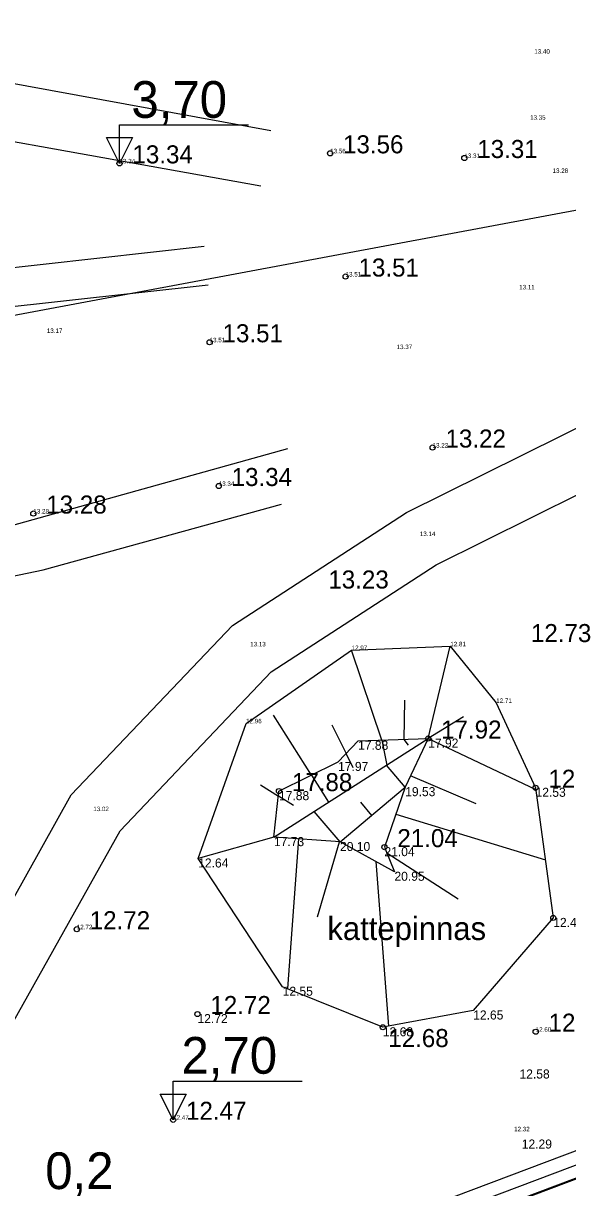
# Model space of a CAD drawing. Extents: x 433497 to 434382, y 6534486 to 6534993.
# Drawn here: x 433653.5 to 433695.8, y 6534629.3 to 6534719.6 of the extents above; entities that cross this region are included whole.
import ezdxf

# ---------------------------------------------------------------- set-up
doc = ezdxf.new("R2010")
doc.units = 0
for name, color, linetype in [('Default', 7, 'Continuous'), ('GEOLPUNKT', 7, 'Continuous'), ('jääkpaksus', 7, 'Continuous'), ('kataster', 7, 'Continuous'), ('KORGUS-EH2000', 7, 'Continuous'), ('l__x00e4__bil__x00f5__iked', 7, 'Continuous'), ('MOOTKORG-EH2000', 7, 'Continuous'), ('PIIR', 7, 'Continuous'), ('RELJEEF', 7, 'Continuous'), ('TEE', 7, 'Continuous')]:
    doc.layers.add(name, color=color, linetype=linetype)

msp = doc.modelspace()

# ---------------------------------------------------------------- linework, layer by layer
at = {"layer": 'Default'}
msp.add_lwpolyline([(433617.12, 6534791.025), (433632.75, 6534606.045), (434137.38, 6534796.515), (434127.69, 6534855.6), (433968.21, 6534911.925), (433942.38, 6534904.035), (433920.99, 6534907.275)], close=True, dxfattribs=at)
msp.add_lwpolyline([(433617.12, 6534791.025), (433632.75, 6534606.045), (434137.38, 6534796.515), (434127.69, 6534855.6), (433968.21, 6534911.925), (433942.38, 6534904.035), (433920.99, 6534907.275)], close=True, dxfattribs=at)
msp.add_lwpolyline([(433617.12, 6534791.025), (433632.75, 6534606.045), (434137.38, 6534796.515), (434127.69, 6534855.6), (433968.21, 6534911.925), (433942.38, 6534904.035), (433920.99, 6534907.275)], close=True, dxfattribs=at)
at = {"layer": 'jääkpaksus'}
for points in [[(433661.002, 6534708.772), (433661.002, 6534711.772), (433671.002, 6534711.772)], [(433665.157, 6534634.571), (433665.157, 6534637.571), (433675.157, 6534637.571)]]:
    msp.add_lwpolyline(points, dxfattribs=at)
for points in [[(433661.002, 6534708.772), (433660.002, 6534710.772), (433662.002, 6534710.772)], [(433665.157, 6534634.571), (433664.157, 6534636.571), (433666.157, 6534636.571)]]:
    msp.add_lwpolyline(points, close=True, dxfattribs=at)
at = {"layer": 'kataster'}
msp.add_lwpolyline([(433617.102, 6534791.002), (433632.769, 6534606.029), (434137.446, 6534796.469), (434127.827, 6534855.589), (433950.026, 6534918.39)], close=True, dxfattribs=at)
at = {"layer": 'KORGUS-EH2000'}
for centre in [(433677.332, 6534709.553), (433661.002, 6534708.772), (433687.742, 6534709.189), (433678.533, 6534699.993), (433667.988, 6534694.894), (433685.28, 6534686.725), (433668.692, 6534683.743), (433654.318, 6534681.606), (433684.938, 6534664.149), (433673.366, 6534660.07), (433693.262, 6534660.331), (433681.544, 6534655.725), (433694.635, 6534650.236), (433657.686, 6534649.357), (433667.044, 6534642.775), (433681.42, 6534641.752), (433693.272, 6534641.407), (433665.157, 6534634.571)]:
    msp.add_circle(centre, 0.2, dxfattribs=at)
at = {"layer": 'l__x00e4__bil__x00f5__iked'}
msp.add_lwpolyline([(433620.07, 6534691.039), (433627.105, 6534692.187), (433736.834, 6534712.709), (433742.792, 6534710.723), (433822.234, 6534766.498), (433986.579, 6534812.177), (434120.472, 6534848.091), (434132.163, 6534850.175)], dxfattribs=at)
at = {"layer": 'PIIR'}
msp.add_lwpolyline([(433632.732, 6534605.959), (434137.353, 6534796.454), (434127.754, 6534855.539), (433968.208, 6534911.976), (433942.39, 6534904.031), (433921.04, 6534907.341), (433617.174, 6534790.992), (433632.732, 6534605.959)], dxfattribs=at)
for points in [[(433618.234, 6534790.327), (433921.149, 6534906.313), (433942.464, 6534903.008), (433968.187, 6534910.923), (434126.862, 6534854.794), (434136.235, 6534797.101), (433633.617, 6534607.362)], [(433619.24, 6534789.695), (433634.52, 6534608.851), (434135.141, 6534797.808), (434125.908, 6534854.108), (433968.165, 6534909.82), (433942.53, 6534901.99), (433921.212, 6534905.219)], [(433619.24, 6534789.695), (433634.52, 6534608.851), (434135.141, 6534797.808), (434125.908, 6534854.108), (433968.165, 6534909.82), (433942.53, 6534901.99), (433921.212, 6534905.219)]]:
    msp.add_lwpolyline(points, close=True, dxfattribs=at)
at = {"layer": 'RELJEEF'}
for p, q in [((433681.339, 6534664.035), (433679.002, 6534671.016)), ((433684.938, 6534664.149), (433686.652, 6534671.307)), ((433675.885, 6534661.316), (433672.945, 6534665.977)), ((433677.465, 6534665.214), (433678.566, 6534662.989)), ((433687.666, 6534665.838), (433684.938, 6534664.149)), ((433681.339, 6534664.035), (433681.725, 6534662.095)), ((433684.938, 6534664.149), (433693.28, 6534660.196)), ((433684.938, 6534664.149), (433684.938, 6534664.149)), ((433679.113, 6534661.882), (433678.566, 6534662.989)), ((433683.152, 6534660.38), (433681.714, 6534662.088)), ((433675.885, 6534661.316), (433677.213, 6534659.211)), ((433688.647, 6534659.084), (433683.568, 6534661.257)), ((433671.929, 6534660.55), (433673.324, 6534659.683)), ((433674.497, 6534658.954), (433673.324, 6534659.683)), ((433679.683, 6534659.212), (433680.546, 6534658.187)), ((433678.098, 6534656.126), (433676.1, 6534658.5)), ((433682.424, 6534658.273), (433694.022, 6534654.742)), ((433672.975, 6534656.502), (433667.099, 6534654.848)), ((433672.975, 6534656.502), (433672.975, 6534656.502)), ((433674.873, 6534656.363), (433674.021, 6534644.748)), ((433676.361, 6534650.309), (433678.064, 6534656.128)), ((433687.267, 6534651.686), (433681.734, 6534655.258)), ((433680.876, 6534654.606), (433681.856, 6534641.833))]:
    msp.add_line(p, q, dxfattribs=at)
for points in [[(433673.651, 6534644.898), (433667.099, 6534654.848), (433670.815, 6534665.331), (433679.002, 6534671.016), (433686.652, 6534671.307)], [(433686.652, 6534671.307), (433690.214, 6534666.912), (433693.262, 6534660.331), (433694.635, 6534650.236), (433688.426, 6534643.053), (433681.42, 6534641.752), (433673.651, 6534644.898)], [(433683.111, 6534667.117), (433683.05, 6534664.089), (433683.387, 6534663.636)], [(433684.938, 6534664.149), (433683.152, 6534660.38), (433681.544, 6534655.725), (433682.319, 6534653.817), (433678.098, 6534656.126), (433672.975, 6534656.502)], [(433672.975, 6534656.502), (433673.366, 6534660.07), (433677.95, 6534662.337), (433679.5, 6534663.977), (433684.938, 6534664.149)], [(433672.975, 6534656.502), (433684.938, 6534664.149)], [(433678.098, 6534656.126), (433683.152, 6534660.38)]]:
    msp.add_lwpolyline(points, dxfattribs=at)
at = {"layer": 'TEE'}
for points in [[(433629.62, 6534620.933), (433635.717, 6534625.88), (433648.001, 6534643.205), (433657.255, 6534659.779), (433669.771, 6534672.932), (433683.244, 6534681.694), (433698.319, 6534689.166), (433713.422, 6534698.28), (433725.167, 6534710.357), (433749.242, 6534742.46), (433772.059, 6534766.624), (433790.138, 6534781.288), (433800.698, 6534786.54), (433824.398, 6534799.304), (433830.425, 6534802.129), (433845.699, 6534809.155)], [(433604.844, 6534600.897), (433614.152, 6534605.53), (433628.909, 6534614.355), (433639.149, 6534622.663), (433651.948, 6534640.714), (433661.037, 6534656.993), (433672.77, 6534669.323), (433685.557, 6534677.639), (433700.561, 6534685.076), (433716.344, 6534694.6), (433728.716, 6534707.321), (433752.812, 6534739.453), (433775.036, 6534762.988), (433798.049, 6534780.902), (433815.08, 6534789.81), (433832.403, 6534797.909), (433848.041, 6534804.286)], [(433672.734, 6534711.298), (433651.979, 6534715.092), (433635.59, 6534718.088), (433619.528, 6534719.24), (433607.766, 6534719.344), (433594.957, 6534719.456), (433591.29, 6534719.074)], [(433591.695, 6534715.087), (433595.257, 6534715.296), (433620.868, 6534715.296), (433636.169, 6534713.432), (433671.959, 6534707.042)], [(433667.554, 6534702.314), (433650.896, 6534700.47), (433641.36, 6534699.188), (433629.118, 6534697.444), (433621.778, 6534696.4), (433614.994, 6534694.81)], [(433667.884, 6534699.332), (433651.26, 6534697.492), (433641.772, 6534696.216), (433629.54, 6534694.474), (433622.332, 6534693.448), (433615.678, 6534691.89)], [(433674.034, 6534686.64), (433639.241, 6534676.921), (433623.251, 6534673.364), (433596.219, 6534670.456)], [(433596.597, 6534666.727), (433624.447, 6534670.155), (433640.413, 6534674.187), (433655.086, 6534677.23), (433673.552, 6534682.346)]]:
    msp.add_lwpolyline(points, dxfattribs=at)

# ---------------------------------------------------------------- texts
at = {"layer": 'GEOLPUNKT'}
msp.add_text('0,2', height=2.85, dxfattribs=at).set_placement((433655.24, 6534629.196))
at = {"layer": 'jääkpaksus'}
for s, p in [('3,70', (433661.922, 6534712.305)), (' 2,70', (433664.745, 6534638.146))]:
    msp.add_text(s, height=2.85, rotation=360, dxfattribs=at).set_placement(p)
at = {"layer": 'KORGUS-EH2000'}
for s, p in [('13.56', (433678.332, 6534709.553)), ('13.31', (433688.742, 6534709.189)), ('13.34', (433662.002, 6534708.772)), ('13.51', (433679.533, 6534699.993)), ('13.51', (433668.988, 6534694.894)), ('13.22', (433686.28, 6534686.725)), ('13.34', (433669.692, 6534683.743)), ('13.28', (433655.318, 6534681.606)), ('13.23', (433677.195, 6534675.791)), ('12.73', (433692.904, 6534671.633)), ('17.92', (433685.938, 6534664.149)), ('12.53', (433694.262, 6534660.331)), ('17.88', (433674.366, 6534660.07)), ('21.04', (433682.544, 6534655.725)), ('12.72', (433658.686, 6534649.357)), ('12.72', (433668.044, 6534642.775)), ('12.60', (433694.272, 6534641.407)), ('12.68', (433681.84, 6534640.216)), ('12.47', (433666.157, 6534634.571))]:
    msp.add_text(s, height=1.4, dxfattribs=at).set_placement(p)
at = {"layer": 'MOOTKORG-EH2000'}
for s, height, p in [('13.40', 0.35, (433693.164, 6534717.285)), ('13.35', 0.35, (433692.836, 6534712.157)), ('13.56', 0.35, (433677.332, 6534709.553)), ('13.31', 0.35, (433687.742, 6534709.189)), ('13.34', 0.35, (433661.002, 6534708.772)), ('13.28', 0.35, (433694.583, 6534708.03)), ('13.51', 0.35, (433678.533, 6534699.993)), ('13.11', 0.35, (433691.987, 6534698.997)), ('13.17', 0.35, (433655.361, 6534695.615)), ('13.51', 0.35, (433667.988, 6534694.894)), ('13.37', 0.35, (433682.486, 6534694.364)), ('13.22', 0.35, (433685.28, 6534686.725)), ('13.34', 0.35, (433668.692, 6534683.743)), ('13.28', 0.35, (433654.318, 6534681.606)), ('13.14', 0.35, (433684.289, 6534679.862)), ('13.13', 0.35, (433671.126, 6534671.301)), ('12.81', 0.35, (433686.652, 6534671.307)), ('12.97', 0.35, (433679.002, 6534671.016)), ('12.71', 0.35, (433690.214, 6534666.912)), ('12.96', 0.35, (433670.815, 6534665.331)), ('17.88', 0.7, (433679.5, 6534663.277)), ('17.92', 0.7, (433684.938, 6534663.449)), ('17.97', 0.7, (433677.95, 6534661.637)), ('17.88', 0.7, (433673.366, 6534659.37)), ('19.53', 0.7, (433683.152, 6534659.68)), ('12.53', 0.7, (433693.262, 6534659.631)), ('13.02', 0.35, (433658.964, 6534658.52)), ('17.73', 0.7, (433672.975, 6534655.802)), ('20.10', 0.7, (433678.098, 6534655.426)), ('21.04', 0.7, (433681.544, 6534655.025)), ('12.64', 0.7, (433667.099, 6534654.148)), ('20.95', 0.7, (433682.319, 6534653.117)), ('12.43', 0.7, (433694.635, 6534649.536)), ('12.72', 0.35, (433657.686, 6534649.357)), ('12.55', 0.7, (433673.651, 6534644.198)), ('12.72', 0.7, (433667.044, 6534642.075)), ('12.65', 0.7, (433688.426, 6534642.353)), ('12.68', 0.7, (433681.42, 6534641.052)), ('12.60', 0.35, (433693.272, 6534641.407)), ('12.58', 0.7, (433692.018, 6534637.776)), ('12.47', 0.35, (433665.157, 6534634.571)), ('12.32', 0.35, (433691.599, 6534633.679)), ('12.29', 0.7, (433692.191, 6534632.343))]:
    msp.add_text(s, height=height, dxfattribs=at).set_placement(p)
at = {"layer": 'RELJEEF'}
msp.add_text('kattepinnas', height=1.8, dxfattribs=at).set_placement((433677.117, 6534648.519))

doc.saveas('drawing.dxf')
